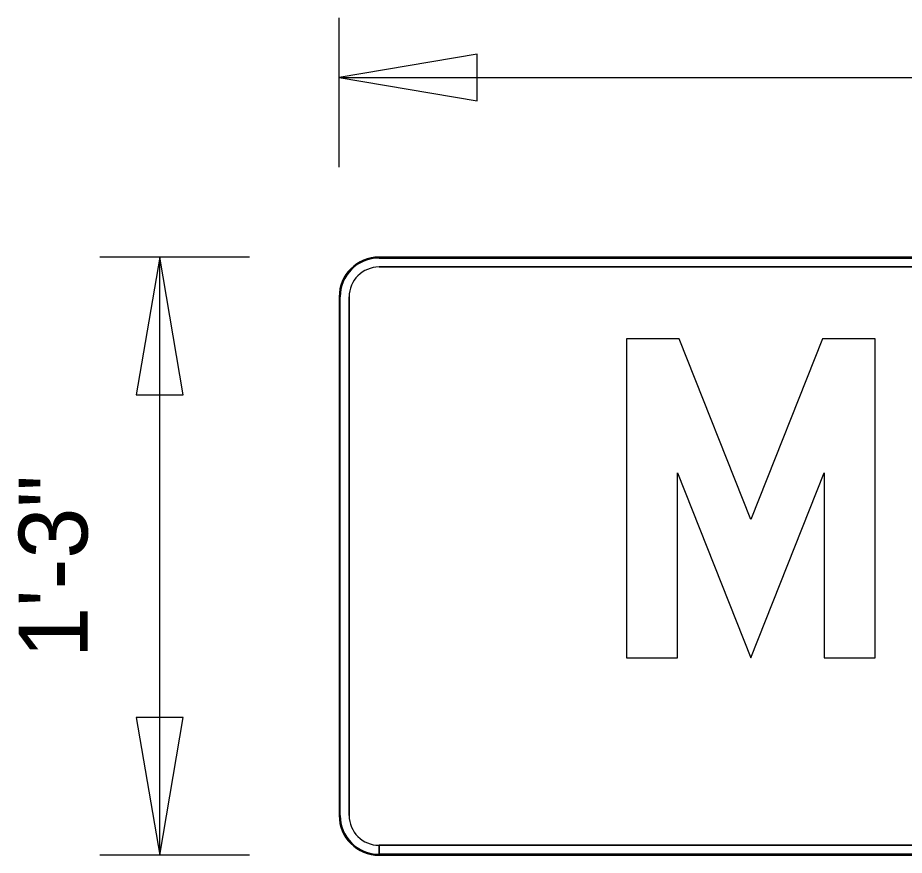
# Model space of a CAD drawing. Extents: x 0 to 770, y 0 to 495.
# Drawn here: x 393.7 to 438.81, y 417.89 to 460.51 of the extents above; entities that cross this region are included whole.
import ezdxf

# ---------------------------------------------------------------- set-up
doc = ezdxf.new("R2010")
doc.units = 0
for name, color, linetype in [('Dimension', 7, 'Continuous'), ('GSBWFill', 7, 'Continuous'), ('GSColorFill', 7, 'Continuous'), ('GSDims', 7, 'Continuous'), ('GSOutline', 7, 'Continuous'), ('TextStructures', 7, 'Continuous')]:
    doc.layers.add(name, color=color, linetype=linetype)

msp = doc.modelspace()

# ---------------------------------------------------------------- linework, layer by layer
at = {"layer": 'Dimension'}
for points in [[(410.054, 457.47), (417.071, 456.281), (417.071, 458.659)], [(400.92, 448.336), (399.731, 441.319), (402.109, 441.319)], [(400.92, 417.888), (402.109, 424.904), (399.731, 424.904)]]:
    msp.add_lwpolyline(points, close=True, dxfattribs=at)
at = {"layer": 'GSBWFill'}
for p, q in [((541.995, 448.336), (412.084, 448.336)), ((541.995, 448.336), (412.084, 448.336)), ((412.084, 447.828), (541.995, 447.828)), ((410.054, 446.306), (410.054, 419.918)), ((410.054, 446.306), (410.054, 419.918)), ((410.562, 419.918), (410.562, 446.306)), ((412.084, 417.888), (412.084, 418.395)), ((541.995, 418.395), (412.089, 418.395)), ((412.089, 418.395), (412.089, 417.888)), ((412.084, 417.888), (541.995, 417.888)), ((412.089, 417.888), (541.995, 417.888))]:
    msp.add_line(p, q, dxfattribs=at)
msp.add_lwpolyline([(437.335, 427.936), (437.335, 444.174), (434.647, 444.174), (431.002, 434.984), (427.358, 444.174), (424.669, 444.174), (424.669, 427.936), (427.267, 427.936), (427.267, 437.354), (431.002, 427.936), (434.737, 437.354), (434.737, 427.936)], close=True, dxfattribs=at)
for centre, radius, start, end in [((412.084, 446.306), 2.03, 90, 180), ((412.084, 446.306), 2.03, 90, 180), ((412.084, 446.306), 1.522, 90, 180), ((412.084, 419.918), 2.03, 180, 270), ((412.084, 419.918), 2.03, 180, 270), ((412.084, 419.918), 1.522, 180, 270)]:
    msp.add_arc(centre, radius, start, end, dxfattribs=at)
at = {"layer": 'GSColorFill'}
for p, q in [((541.995, 448.336), (412.084, 448.336)), ((541.995, 448.336), (412.084, 448.336)), ((541.995, 448.336), (412.084, 448.336)), ((412.084, 448.285), (541.995, 448.285)), ((412.084, 447.828), (541.995, 447.828)), ((410.054, 446.306), (410.054, 419.918)), ((410.054, 446.306), (410.054, 419.918)), ((410.054, 446.306), (410.054, 419.918)), ((410.105, 419.918), (410.105, 446.306)), ((410.562, 419.918), (410.562, 446.306)), ((412.084, 417.888), (412.084, 418.395)), ((541.995, 418.395), (412.089, 418.395)), ((412.089, 418.395), (412.089, 417.888)), ((412.084, 417.888), (412.084, 417.938)), ((412.084, 417.888), (541.995, 417.888)), ((541.995, 417.938), (412.085, 417.938)), ((412.085, 417.938), (412.085, 417.888)), ((412.085, 417.888), (541.995, 417.888)), ((412.089, 417.888), (541.995, 417.888))]:
    msp.add_line(p, q, dxfattribs=at)
msp.add_lwpolyline([(437.335, 427.936), (437.335, 444.174), (434.647, 444.174), (431.002, 434.984), (427.358, 444.174), (424.669, 444.174), (424.669, 427.936), (427.267, 427.936), (427.267, 437.354), (431.002, 427.936), (434.737, 437.354), (434.737, 427.936)], close=True, dxfattribs=at)
for centre, radius, start, end in [((412.084, 446.306), 2.03, 90, 180), ((412.084, 446.306), 2.03, 90, 180), ((412.084, 446.306), 2.03, 90, 180), ((412.084, 446.306), 1.979, 90, 180), ((412.084, 446.306), 1.522, 90, 180), ((412.084, 419.918), 2.03, 180, 270), ((412.084, 419.918), 2.03, 180, 270), ((412.084, 419.918), 2.03, 180, 270), ((412.084, 419.918), 1.979, 180, 270), ((412.084, 419.918), 1.522, 180, 270)]:
    msp.add_arc(centre, radius, start, end, dxfattribs=at)
at = {"layer": 'GSDims'}
for p, q in [((410.054, 452.903), (410.054, 460.515)), ((410.054, 457.47), (544.025, 457.47)), ((405.487, 448.336), (397.875, 448.336)), ((400.92, 417.888), (400.92, 448.336)), ((405.487, 417.888), (397.875, 417.888))]:
    msp.add_line(p, q, dxfattribs=at)
at = {"layer": 'GSOutline'}
for p, q in [((541.995, 448.336), (412.084, 448.336)), ((541.995, 448.336), (412.084, 448.336)), ((541.995, 447.828), (412.084, 447.828)), ((410.054, 446.306), (410.054, 419.918)), ((410.054, 446.306), (410.054, 419.918)), ((410.562, 446.306), (410.562, 419.918)), ((412.084, 418.395), (541.995, 418.395)), ((412.084, 417.888), (541.995, 417.888)), ((412.084, 417.888), (541.995, 417.888))]:
    msp.add_line(p, q, dxfattribs=at)
msp.add_lwpolyline([(437.335, 427.936), (437.335, 444.174), (434.647, 444.174), (431.002, 434.984), (427.358, 444.174), (424.669, 444.174), (424.669, 427.936), (427.267, 427.936), (427.267, 437.354), (431.002, 427.936), (434.737, 437.354), (434.737, 427.936)], close=True, dxfattribs=at)
for centre, radius, start, end in [((412.084, 446.306), 2.03, 90, 180), ((412.084, 446.306), 2.03, 90, 180), ((412.084, 446.306), 1.522, 90, 180), ((412.084, 419.918), 2.03, 180, 270), ((412.084, 419.918), 2.03, 180, 270), ((412.084, 419.918), 1.522, 180, 270)]:
    msp.add_arc(centre, radius, start, end, dxfattribs=at)

# ---------------------------------------------------------------- texts
at = {"layer": 'TextStructures'}
msp.add_text('1\'-3"', height=3.5, rotation=90, dxfattribs=at).set_placement((397.249, 427.926))

doc.saveas('drawing.dxf')
